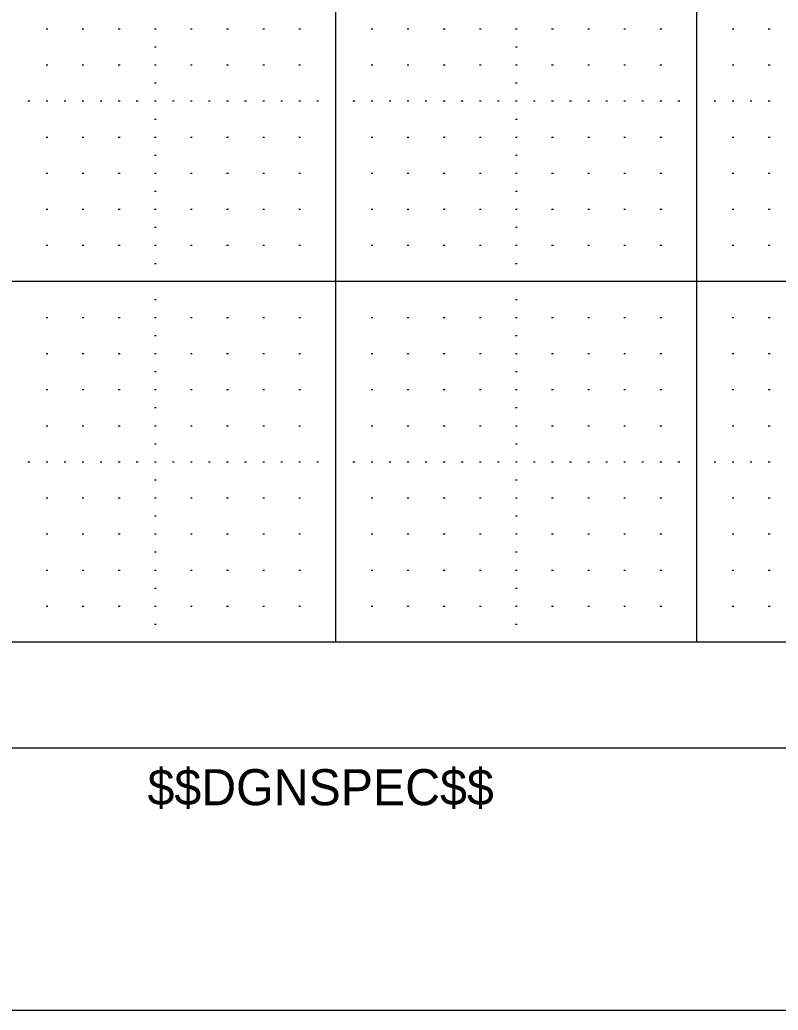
# Model space of a CAD drawing. Extents: x 0 to 34.3, y 0 to 22.
# Drawn here: x 23.468 to 25.568, y 0 to 2.745 of the extents above; entities that cross this region are included whole.
import ezdxf

# ---------------------------------------------------------------- set-up
doc = ezdxf.new("R2010")
doc.units = 0
for name, color, linetype in [('Level 1', 7, 'Continuous'), ('Level 4', 7, 'Continuous'), ('Level 48', 7, 'Continuous'), ('Level 5', 7, 'Continuous'), ('Level 63', 7, 'Continuous'), ('R_Border_Dark', 7, 'Continuous')]:
    doc.layers.add(name, color=color, linetype=linetype)

msp = doc.modelspace()

# ---------------------------------------------------------------- linework, layer by layer
at = {"layer": 'Level 1'}
msp.add_line((33.215, 0.726), (1.597, 0.726), dxfattribs=at)
msp.add_lwpolyline([(2.343, 9.02), (32.343, 9.02), (32.343, 1.02), (2.343, 1.02)], close=True, dxfattribs=at)
at = {"layer": 'Level 4'}
msp.add_line((33.215, 1.02), (1.597, 1.02), dxfattribs=at)
at = {"layer": 'Level 5'}
for p, q in [((23.5405, 2.72), (23.5455, 2.72)), ((23.6405, 2.72), (23.6455, 2.72)), ((23.7405, 2.72), (23.7455, 2.72)), ((23.8405, 2.72), (23.8455, 2.72)), ((23.9405, 2.72), (23.9455, 2.72)), ((24.0405, 2.72), (24.0455, 2.72)), ((24.1405, 2.72), (24.1455, 2.72)), ((24.2405, 2.72), (24.2455, 2.72)), ((24.4405, 2.72), (24.4455, 2.72)), ((24.5405, 2.72), (24.5455, 2.72)), ((24.6405, 2.72), (24.6455, 2.72)), ((24.7405, 2.72), (24.7455, 2.72)), ((24.8405, 2.72), (24.8455, 2.72)), ((24.9405, 2.72), (24.9455, 2.72)), ((25.0405, 2.72), (25.0455, 2.72)), ((25.1405, 2.72), (25.1455, 2.72)), ((25.2405, 2.72), (25.2455, 2.72)), ((25.4405, 2.72), (25.4455, 2.72)), ((25.5405, 2.72), (25.5455, 2.72)), ((23.8405, 2.67), (23.8455, 2.67)), ((24.8405, 2.67), (24.8455, 2.67)), ((23.5405, 2.62), (23.5455, 2.62)), ((23.6405, 2.62), (23.6455, 2.62)), ((23.7405, 2.62), (23.7455, 2.62)), ((23.8405, 2.62), (23.8455, 2.62)), ((23.9405, 2.62), (23.9455, 2.62)), ((24.0405, 2.62), (24.0455, 2.62)), ((24.1405, 2.62), (24.1455, 2.62)), ((24.2405, 2.62), (24.2455, 2.62)), ((24.4405, 2.62), (24.4455, 2.62)), ((24.5405, 2.62), (24.5455, 2.62)), ((24.6405, 2.62), (24.6455, 2.62)), ((24.7405, 2.62), (24.7455, 2.62)), ((24.8405, 2.62), (24.8455, 2.62)), ((24.9405, 2.62), (24.9455, 2.62)), ((25.0405, 2.62), (25.0455, 2.62)), ((25.1405, 2.62), (25.1455, 2.62)), ((25.2405, 2.62), (25.2455, 2.62)), ((25.4405, 2.62), (25.4455, 2.62)), ((25.5405, 2.62), (25.5455, 2.62)), ((23.8405, 2.57), (23.8455, 2.57)), ((24.8405, 2.57), (24.8455, 2.57)), ((23.4905, 2.52), (23.4955, 2.52)), ((23.5405, 2.52), (23.5455, 2.52)), ((23.5905, 2.52), (23.5955, 2.52)), ((23.6405, 2.52), (23.6455, 2.52)), ((23.6905, 2.52), (23.6955, 2.52)), ((23.7405, 2.52), (23.7455, 2.52)), ((23.7905, 2.52), (23.7955, 2.52)), ((23.8405, 2.52), (23.8455, 2.52)), ((23.8905, 2.52), (23.8955, 2.52)), ((23.9405, 2.52), (23.9455, 2.52)), ((23.9905, 2.52), (23.9955, 2.52)), ((24.0405, 2.52), (24.0455, 2.52)), ((24.0905, 2.52), (24.0955, 2.52)), ((24.1405, 2.52), (24.1455, 2.52)), ((24.1905, 2.52), (24.1955, 2.52)), ((24.2405, 2.52), (24.2455, 2.52)), ((24.2905, 2.52), (24.2955, 2.52)), ((24.3905, 2.52), (24.3955, 2.52)), ((24.4405, 2.52), (24.4455, 2.52)), ((24.4905, 2.52), (24.4955, 2.52)), ((24.5405, 2.52), (24.5455, 2.52)), ((24.5905, 2.52), (24.5955, 2.52)), ((24.6405, 2.52), (24.6455, 2.52)), ((24.6905, 2.52), (24.6955, 2.52)), ((24.7405, 2.52), (24.7455, 2.52)), ((24.7905, 2.52), (24.7955, 2.52)), ((24.8405, 2.52), (24.8455, 2.52)), ((24.8905, 2.52), (24.8955, 2.52)), ((24.9405, 2.52), (24.9455, 2.52)), ((24.9905, 2.52), (24.9955, 2.52)), ((25.0405, 2.52), (25.0455, 2.52)), ((25.0905, 2.52), (25.0955, 2.52)), ((25.1405, 2.52), (25.1455, 2.52)), ((25.1905, 2.52), (25.1955, 2.52)), ((25.2405, 2.52), (25.2455, 2.52)), ((25.2905, 2.52), (25.2955, 2.52)), ((25.3905, 2.52), (25.3955, 2.52)), ((25.4405, 2.52), (25.4455, 2.52)), ((25.4905, 2.52), (25.4955, 2.52)), ((25.5405, 2.52), (25.5455, 2.52)), ((23.8405, 2.47), (23.8455, 2.47)), ((24.8405, 2.47), (24.8455, 2.47)), ((23.5405, 2.42), (23.5455, 2.42)), ((23.6405, 2.42), (23.6455, 2.42)), ((23.7405, 2.42), (23.7455, 2.42)), ((23.8405, 2.42), (23.8455, 2.42)), ((23.9405, 2.42), (23.9455, 2.42)), ((24.0405, 2.42), (24.0455, 2.42)), ((24.1405, 2.42), (24.1455, 2.42)), ((24.2405, 2.42), (24.2455, 2.42)), ((24.4405, 2.42), (24.4455, 2.42)), ((24.5405, 2.42), (24.5455, 2.42)), ((24.6405, 2.42), (24.6455, 2.42)), ((24.7405, 2.42), (24.7455, 2.42)), ((24.8405, 2.42), (24.8455, 2.42)), ((24.9405, 2.42), (24.9455, 2.42)), ((25.0405, 2.42), (25.0455, 2.42)), ((25.1405, 2.42), (25.1455, 2.42)), ((25.2405, 2.42), (25.2455, 2.42)), ((25.4405, 2.42), (25.4455, 2.42)), ((25.5405, 2.42), (25.5455, 2.42)), ((23.8405, 2.37), (23.8455, 2.37)), ((24.8405, 2.37), (24.8455, 2.37)), ((23.5405, 2.32), (23.5455, 2.32)), ((23.6405, 2.32), (23.6455, 2.32)), ((23.7405, 2.32), (23.7455, 2.32)), ((23.8405, 2.32), (23.8455, 2.32)), ((23.9405, 2.32), (23.9455, 2.32)), ((24.0405, 2.32), (24.0455, 2.32)), ((24.1405, 2.32), (24.1455, 2.32)), ((24.2405, 2.32), (24.2455, 2.32)), ((24.4405, 2.32), (24.4455, 2.32)), ((24.5405, 2.32), (24.5455, 2.32)), ((24.6405, 2.32), (24.6455, 2.32)), ((24.7405, 2.32), (24.7455, 2.32)), ((24.8405, 2.32), (24.8455, 2.32)), ((24.9405, 2.32), (24.9455, 2.32)), ((25.0405, 2.32), (25.0455, 2.32)), ((25.1405, 2.32), (25.1455, 2.32)), ((25.2405, 2.32), (25.2455, 2.32)), ((25.4405, 2.32), (25.4455, 2.32)), ((25.5405, 2.32), (25.5455, 2.32)), ((23.8405, 2.27), (23.8455, 2.27)), ((24.8405, 2.27), (24.8455, 2.27)), ((23.5405, 2.22), (23.5455, 2.22)), ((23.6405, 2.22), (23.6455, 2.22)), ((23.7405, 2.22), (23.7455, 2.22)), ((23.8405, 2.22), (23.8455, 2.22)), ((23.9405, 2.22), (23.9455, 2.22)), ((24.0405, 2.22), (24.0455, 2.22)), ((24.1405, 2.22), (24.1455, 2.22)), ((24.2405, 2.22), (24.2455, 2.22)), ((24.4405, 2.22), (24.4455, 2.22)), ((24.5405, 2.22), (24.5455, 2.22)), ((24.6405, 2.22), (24.6455, 2.22)), ((24.7405, 2.22), (24.7455, 2.22)), ((24.8405, 2.22), (24.8455, 2.22)), ((24.9405, 2.22), (24.9455, 2.22)), ((25.0405, 2.22), (25.0455, 2.22)), ((25.1405, 2.22), (25.1455, 2.22)), ((25.2405, 2.22), (25.2455, 2.22)), ((25.4405, 2.22), (25.4455, 2.22)), ((25.5405, 2.22), (25.5455, 2.22)), ((23.8405, 2.17), (23.8455, 2.17)), ((24.8405, 2.17), (24.8455, 2.17)), ((23.5405, 2.12), (23.5455, 2.12)), ((23.6405, 2.12), (23.6455, 2.12)), ((23.7405, 2.12), (23.7455, 2.12)), ((23.8405, 2.12), (23.8455, 2.12)), ((23.9405, 2.12), (23.9455, 2.12)), ((24.0405, 2.12), (24.0455, 2.12)), ((24.1405, 2.12), (24.1455, 2.12)), ((24.2405, 2.12), (24.2455, 2.12)), ((24.4405, 2.12), (24.4455, 2.12)), ((24.5405, 2.12), (24.5455, 2.12)), ((24.6405, 2.12), (24.6455, 2.12)), ((24.7405, 2.12), (24.7455, 2.12)), ((24.8405, 2.12), (24.8455, 2.12)), ((24.9405, 2.12), (24.9455, 2.12)), ((25.0405, 2.12), (25.0455, 2.12)), ((25.1405, 2.12), (25.1455, 2.12)), ((25.2405, 2.12), (25.2455, 2.12)), ((25.4405, 2.12), (25.4455, 2.12)), ((25.5405, 2.12), (25.5455, 2.12)), ((23.8405, 2.07), (23.8455, 2.07)), ((24.8405, 2.07), (24.8455, 2.07)), ((23.8405, 1.97), (23.8455, 1.97)), ((24.8405, 1.97), (24.8455, 1.97)), ((23.5405, 1.92), (23.5455, 1.92)), ((23.6405, 1.92), (23.6455, 1.92)), ((23.7405, 1.92), (23.7455, 1.92)), ((23.8405, 1.92), (23.8455, 1.92)), ((23.9405, 1.92), (23.9455, 1.92)), ((24.0405, 1.92), (24.0455, 1.92)), ((24.1405, 1.92), (24.1455, 1.92)), ((24.2405, 1.92), (24.2455, 1.92)), ((24.4405, 1.92), (24.4455, 1.92)), ((24.5405, 1.92), (24.5455, 1.92)), ((24.6405, 1.92), (24.6455, 1.92)), ((24.7405, 1.92), (24.7455, 1.92)), ((24.8405, 1.92), (24.8455, 1.92)), ((24.9405, 1.92), (24.9455, 1.92)), ((25.0405, 1.92), (25.0455, 1.92)), ((25.1405, 1.92), (25.1455, 1.92)), ((25.2405, 1.92), (25.2455, 1.92)), ((25.4405, 1.92), (25.4455, 1.92)), ((25.5405, 1.92), (25.5455, 1.92)), ((23.8405, 1.87), (23.8455, 1.87)), ((24.8405, 1.87), (24.8455, 1.87)), ((23.5405, 1.82), (23.5455, 1.82)), ((23.6405, 1.82), (23.6455, 1.82)), ((23.7405, 1.82), (23.7455, 1.82)), ((23.8405, 1.82), (23.8455, 1.82)), ((23.9405, 1.82), (23.9455, 1.82)), ((24.0405, 1.82), (24.0455, 1.82)), ((24.1405, 1.82), (24.1455, 1.82)), ((24.2405, 1.82), (24.2455, 1.82)), ((24.4405, 1.82), (24.4455, 1.82)), ((24.5405, 1.82), (24.5455, 1.82)), ((24.6405, 1.82), (24.6455, 1.82)), ((24.7405, 1.82), (24.7455, 1.82)), ((24.8405, 1.82), (24.8455, 1.82)), ((24.9405, 1.82), (24.9455, 1.82)), ((25.0405, 1.82), (25.0455, 1.82)), ((25.1405, 1.82), (25.1455, 1.82)), ((25.2405, 1.82), (25.2455, 1.82)), ((25.4405, 1.82), (25.4455, 1.82)), ((25.5405, 1.82), (25.5455, 1.82)), ((23.8405, 1.77), (23.8455, 1.77)), ((24.8405, 1.77), (24.8455, 1.77)), ((23.5405, 1.72), (23.5455, 1.72)), ((23.6405, 1.72), (23.6455, 1.72)), ((23.7405, 1.72), (23.7455, 1.72)), ((23.8405, 1.72), (23.8455, 1.72)), ((23.9405, 1.72), (23.9455, 1.72)), ((24.0405, 1.72), (24.0455, 1.72)), ((24.1405, 1.72), (24.1455, 1.72)), ((24.2405, 1.72), (24.2455, 1.72)), ((24.4405, 1.72), (24.4455, 1.72)), ((24.5405, 1.72), (24.5455, 1.72)), ((24.6405, 1.72), (24.6455, 1.72)), ((24.7405, 1.72), (24.7455, 1.72)), ((24.8405, 1.72), (24.8455, 1.72)), ((24.9405, 1.72), (24.9455, 1.72)), ((25.0405, 1.72), (25.0455, 1.72)), ((25.1405, 1.72), (25.1455, 1.72)), ((25.2405, 1.72), (25.2455, 1.72)), ((25.4405, 1.72), (25.4455, 1.72)), ((25.5405, 1.72), (25.5455, 1.72)), ((23.8405, 1.67), (23.8455, 1.67)), ((24.8405, 1.67), (24.8455, 1.67)), ((23.5405, 1.62), (23.5455, 1.62)), ((23.6405, 1.62), (23.6455, 1.62)), ((23.7405, 1.62), (23.7455, 1.62)), ((23.8405, 1.62), (23.8455, 1.62)), ((23.9405, 1.62), (23.9455, 1.62)), ((24.0405, 1.62), (24.0455, 1.62)), ((24.1405, 1.62), (24.1455, 1.62)), ((24.2405, 1.62), (24.2455, 1.62)), ((24.4405, 1.62), (24.4455, 1.62)), ((24.5405, 1.62), (24.5455, 1.62)), ((24.6405, 1.62), (24.6455, 1.62)), ((24.7405, 1.62), (24.7455, 1.62)), ((24.8405, 1.62), (24.8455, 1.62)), ((24.9405, 1.62), (24.9455, 1.62)), ((25.0405, 1.62), (25.0455, 1.62)), ((25.1405, 1.62), (25.1455, 1.62)), ((25.2405, 1.62), (25.2455, 1.62)), ((25.4405, 1.62), (25.4455, 1.62)), ((25.5405, 1.62), (25.5455, 1.62)), ((23.8405, 1.57), (23.8455, 1.57)), ((24.8405, 1.57), (24.8455, 1.57)), ((23.4905, 1.52), (23.4955, 1.52)), ((23.5405, 1.52), (23.5455, 1.52)), ((23.5905, 1.52), (23.5955, 1.52)), ((23.6405, 1.52), (23.6455, 1.52)), ((23.6905, 1.52), (23.6955, 1.52)), ((23.7405, 1.52), (23.7455, 1.52)), ((23.7905, 1.52), (23.7955, 1.52)), ((23.8405, 1.52), (23.8455, 1.52)), ((23.8905, 1.52), (23.8955, 1.52)), ((23.9405, 1.52), (23.9455, 1.52)), ((23.9905, 1.52), (23.9955, 1.52)), ((24.0405, 1.52), (24.0455, 1.52)), ((24.0905, 1.52), (24.0955, 1.52)), ((24.1405, 1.52), (24.1455, 1.52)), ((24.1905, 1.52), (24.1955, 1.52)), ((24.2405, 1.52), (24.2455, 1.52)), ((24.2905, 1.52), (24.2955, 1.52)), ((24.3905, 1.52), (24.3955, 1.52)), ((24.4405, 1.52), (24.4455, 1.52)), ((24.4905, 1.52), (24.4955, 1.52)), ((24.5405, 1.52), (24.5455, 1.52)), ((24.5905, 1.52), (24.5955, 1.52)), ((24.6405, 1.52), (24.6455, 1.52)), ((24.6905, 1.52), (24.6955, 1.52)), ((24.7405, 1.52), (24.7455, 1.52)), ((24.7905, 1.52), (24.7955, 1.52)), ((24.8405, 1.52), (24.8455, 1.52)), ((24.8905, 1.52), (24.8955, 1.52)), ((24.9405, 1.52), (24.9455, 1.52)), ((24.9905, 1.52), (24.9955, 1.52)), ((25.0405, 1.52), (25.0455, 1.52)), ((25.0905, 1.52), (25.0955, 1.52)), ((25.1405, 1.52), (25.1455, 1.52)), ((25.1905, 1.52), (25.1955, 1.52)), ((25.2405, 1.52), (25.2455, 1.52)), ((25.2905, 1.52), (25.2955, 1.52)), ((25.3905, 1.52), (25.3955, 1.52)), ((25.4405, 1.52), (25.4455, 1.52)), ((25.4905, 1.52), (25.4955, 1.52)), ((25.5405, 1.52), (25.5455, 1.52)), ((23.8405, 1.47), (23.8455, 1.47)), ((24.8405, 1.47), (24.8455, 1.47)), ((23.5405, 1.42), (23.5455, 1.42)), ((23.6405, 1.42), (23.6455, 1.42)), ((23.7405, 1.42), (23.7455, 1.42)), ((23.8405, 1.42), (23.8455, 1.42)), ((23.9405, 1.42), (23.9455, 1.42)), ((24.0405, 1.42), (24.0455, 1.42)), ((24.1405, 1.42), (24.1455, 1.42)), ((24.2405, 1.42), (24.2455, 1.42)), ((24.4405, 1.42), (24.4455, 1.42)), ((24.5405, 1.42), (24.5455, 1.42)), ((24.6405, 1.42), (24.6455, 1.42)), ((24.7405, 1.42), (24.7455, 1.42)), ((24.8405, 1.42), (24.8455, 1.42)), ((24.9405, 1.42), (24.9455, 1.42)), ((25.0405, 1.42), (25.0455, 1.42)), ((25.1405, 1.42), (25.1455, 1.42)), ((25.2405, 1.42), (25.2455, 1.42)), ((25.4405, 1.42), (25.4455, 1.42)), ((25.5405, 1.42), (25.5455, 1.42)), ((23.8405, 1.37), (23.8455, 1.37)), ((24.8405, 1.37), (24.8455, 1.37)), ((23.5405, 1.32), (23.5455, 1.32)), ((23.6405, 1.32), (23.6455, 1.32)), ((23.7405, 1.32), (23.7455, 1.32)), ((23.8405, 1.32), (23.8455, 1.32)), ((23.9405, 1.32), (23.9455, 1.32)), ((24.0405, 1.32), (24.0455, 1.32)), ((24.1405, 1.32), (24.1455, 1.32)), ((24.2405, 1.32), (24.2455, 1.32)), ((24.4405, 1.32), (24.4455, 1.32)), ((24.5405, 1.32), (24.5455, 1.32)), ((24.6405, 1.32), (24.6455, 1.32)), ((24.7405, 1.32), (24.7455, 1.32)), ((24.8405, 1.32), (24.8455, 1.32)), ((24.9405, 1.32), (24.9455, 1.32)), ((25.0405, 1.32), (25.0455, 1.32)), ((25.1405, 1.32), (25.1455, 1.32)), ((25.2405, 1.32), (25.2455, 1.32)), ((25.4405, 1.32), (25.4455, 1.32)), ((25.5405, 1.32), (25.5455, 1.32)), ((23.8405, 1.27), (23.8455, 1.27)), ((24.8405, 1.27), (24.8455, 1.27)), ((23.5405, 1.22), (23.5455, 1.22)), ((23.6405, 1.22), (23.6455, 1.22)), ((23.7405, 1.22), (23.7455, 1.22)), ((23.8405, 1.22), (23.8455, 1.22)), ((23.9405, 1.22), (23.9455, 1.22)), ((24.0405, 1.22), (24.0455, 1.22)), ((24.1405, 1.22), (24.1455, 1.22)), ((24.2405, 1.22), (24.2455, 1.22)), ((24.4405, 1.22), (24.4455, 1.22)), ((24.5405, 1.22), (24.5455, 1.22)), ((24.6405, 1.22), (24.6455, 1.22)), ((24.7405, 1.22), (24.7455, 1.22)), ((24.8405, 1.22), (24.8455, 1.22)), ((24.9405, 1.22), (24.9455, 1.22)), ((25.0405, 1.22), (25.0455, 1.22)), ((25.1405, 1.22), (25.1455, 1.22)), ((25.2405, 1.22), (25.2455, 1.22)), ((25.4405, 1.22), (25.4455, 1.22)), ((25.5405, 1.22), (25.5455, 1.22)), ((23.8405, 1.17), (23.8455, 1.17)), ((24.8405, 1.17), (24.8455, 1.17)), ((23.5405, 1.12), (23.5455, 1.12)), ((23.6405, 1.12), (23.6455, 1.12)), ((23.7405, 1.12), (23.7455, 1.12)), ((23.8405, 1.12), (23.8455, 1.12)), ((23.9405, 1.12), (23.9455, 1.12)), ((24.0405, 1.12), (24.0455, 1.12)), ((24.1405, 1.12), (24.1455, 1.12)), ((24.2405, 1.12), (24.2455, 1.12)), ((24.4405, 1.12), (24.4455, 1.12)), ((24.5405, 1.12), (24.5455, 1.12)), ((24.6405, 1.12), (24.6455, 1.12)), ((24.7405, 1.12), (24.7455, 1.12)), ((24.8405, 1.12), (24.8455, 1.12)), ((24.9405, 1.12), (24.9455, 1.12)), ((25.0405, 1.12), (25.0455, 1.12)), ((25.1405, 1.12), (25.1455, 1.12)), ((25.2405, 1.12), (25.2455, 1.12)), ((25.4405, 1.12), (25.4455, 1.12)), ((25.5405, 1.12), (25.5455, 1.12)), ((23.8405, 1.07), (23.8455, 1.07)), ((24.8405, 1.07), (24.8455, 1.07))]:
    msp.add_line(p, q, dxfattribs=at)
at = {"layer": 'Level 63'}
msp.add_lwpolyline([(0, 0), (34, 0), (34, 22), (0, 22)], close=True, dxfattribs=at)
msp.add_lwpolyline([(32.343, 9.02), (32.343, 1.02), (2.343, 1.02), (2.343, 9.02)], dxfattribs=at)
at = {"layer": 'R_Border_Dark'}
for p, q in [((24.343, 1.02), (24.343, 9.02)), ((25.343, 1.02), (25.343, 9.02)), ((33.215, 2.02), (1.597, 2.02))]:
    msp.add_line(p, q, dxfattribs=at)
msp.add_lwpolyline([(32.343, 9.02), (32.343, 1.02), (2.343, 1.02), (2.343, 9.02)], dxfattribs=at)

# ---------------------------------------------------------------- texts
at = {"layer": 'Level 48'}
msp.add_text('$$DGNSPEC$$', height=0.100002, dxfattribs=at).set_placement((23.8216, 0.568))

doc.saveas('drawing.dxf')
